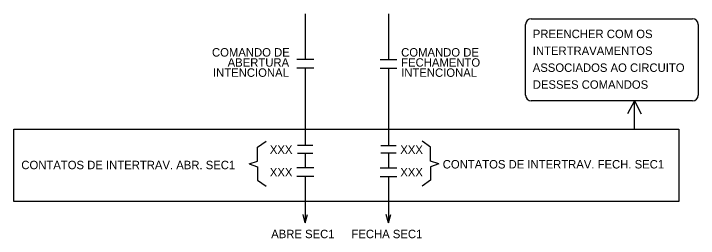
# Model space of a CAD drawing. Extents: x 563 to 1404, y 358 to 952.
# Drawn here: x 1105.8 to 1227.4, y 611.8 to 651.7 of the extents above; entities that cross this region are included whole.
import ezdxf

# ---------------------------------------------------------------- set-up
doc = ezdxf.new("R2010")
doc.units = 0
doc.layers.add('New Level (0)', color=7, linetype='Continuous')

msp = doc.modelspace()

# ---------------------------------------------------------------- linework, layer by layer
for p, q in [((1157.56, 651.7), (1157.56, 643.53)), ((1172.35, 651.7), (1172.35, 643.53)), ((1159.06, 643.53), (1156.06, 643.53)), ((1170.85, 643.53), (1173.85, 643.53)), ((1159.06, 642.03), (1156.06, 642.03)), ((1157.56, 642.03), (1157.56, 628.29)), ((1170.85, 642.03), (1173.85, 642.03)), ((1172.35, 642.03), (1172.35, 628.29)), ((1149.1, 627.97), (1150.6, 629.06)), ((1179.82, 627.97), (1178.32, 629.06)), ((1149.1, 625.51), (1149.1, 627.97)), ((1158.91, 628.29), (1156.21, 628.29)), ((1171, 628.29), (1173.7, 628.29)), ((1179.82, 625.51), (1179.82, 627.97)), ((1156.21, 626.94), (1158.91, 626.94)), ((1157.56, 626.79), (1157.56, 624.28)), ((1173.7, 626.94), (1171, 626.94)), ((1172.35, 626.79), (1172.35, 624.28)), ((1147.6, 625.01), (1149.1, 625.51)), ((1181.32, 625.01), (1179.82, 625.51)), ((1147.6, 625.01), (1149.1, 624.51)), ((1149.1, 624.51), (1149.1, 622.11)), ((1159.06, 624.28), (1156.06, 624.28)), ((1170.85, 624.28), (1173.85, 624.28)), ((1181.32, 625.01), (1179.82, 624.51)), ((1179.82, 624.51), (1179.82, 622.11)), ((1149.1, 622.11), (1150.6, 621.02)), ((1159.06, 622.78), (1156.06, 622.78)), ((1157.56, 622.78), (1157.56, 614.55)), ((1170.85, 622.78), (1173.85, 622.78)), ((1172.35, 622.78), (1172.35, 614.55)), ((1179.82, 622.11), (1178.32, 621.02)), ((1157.56, 614.55), (1157.17, 616)), ((1157.56, 614.55), (1157.95, 616)), ((1172.35, 614.55), (1171.96, 616)), ((1172.35, 614.55), (1172.74, 616))]:
    msp.add_line(p, q)
at = {"layer": 'New Level (0)'}
for p, q in [((1196.72, 637.22), (1196.72, 649.8)), ((1197.72, 650.8), (1226.4, 650.8)), ((1227.4, 649.8), (1227.4, 637.22)), ((1226.4, 636.22), (1197.72, 636.22)), ((1216.05, 636.22), (1214.84, 633.92)), ((1216.05, 631.19), (1216.05, 636.22)), ((1216.05, 636.22), (1217.26, 633.92))]:
    msp.add_line(p, q, dxfattribs=at)
msp.add_lwpolyline([(1105.75, 631.19), (1223.95, 631.19), (1223.95, 618.3), (1105.75, 618.3)], close=True, dxfattribs=at)
for centre, start, end in [((1197.72, 649.8), 90, 180), ((1226.4, 649.8), 0, 90), ((1197.72, 637.22), 180, 270), ((1226.4, 637.22), 270, 0)]:
    msp.add_arc(centre, 1, start, end, dxfattribs=at)

# ---------------------------------------------------------------- texts
for s, p in [('PREENCHER COM OS ', (1197.99, 647.36)), ('COMANDO DE', (1140.99, 644.08)), ('COMANDO DE ', (1174.6, 644.08)), ('INTERTRAVAMENTOS', (1197.99, 644.36)), (' ABERTURA', (1143.21, 642.28)), ('FECHAMENTO ', (1174.6, 642.28)), ('ASSOCIADOS AO CIRCUITO ', (1197.99, 641.36)), (' INTENCIONAL', (1140.61, 640.48)), ('INTENCIONAL', (1174.6, 640.48)), ('DESSES COMANDOS', (1197.99, 638.36)), ('XXX', (1151.27, 626.79)), ('XXX', (1174.45, 626.79)), ('CONTATOS DE INTERTRAV. ABR. SEC1', (1107.11, 624.06)), ('CONTATOS DE INTERTRAV. FECH. SEC1', (1181.99, 624.19)), ('XXX', (1151.27, 622.78)), ('XXX', (1174.45, 622.78)), ('ABRE SEC1', (1151.51, 611.8)), ('FECHA SEC1', (1165.77, 611.8))]:
    msp.add_text(s, height=1.5).set_placement(p)

doc.saveas('drawing.dxf')
